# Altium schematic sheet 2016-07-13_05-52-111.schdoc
size 326 x 125 mm; SheetNumber: 1; SheetTotal: 1
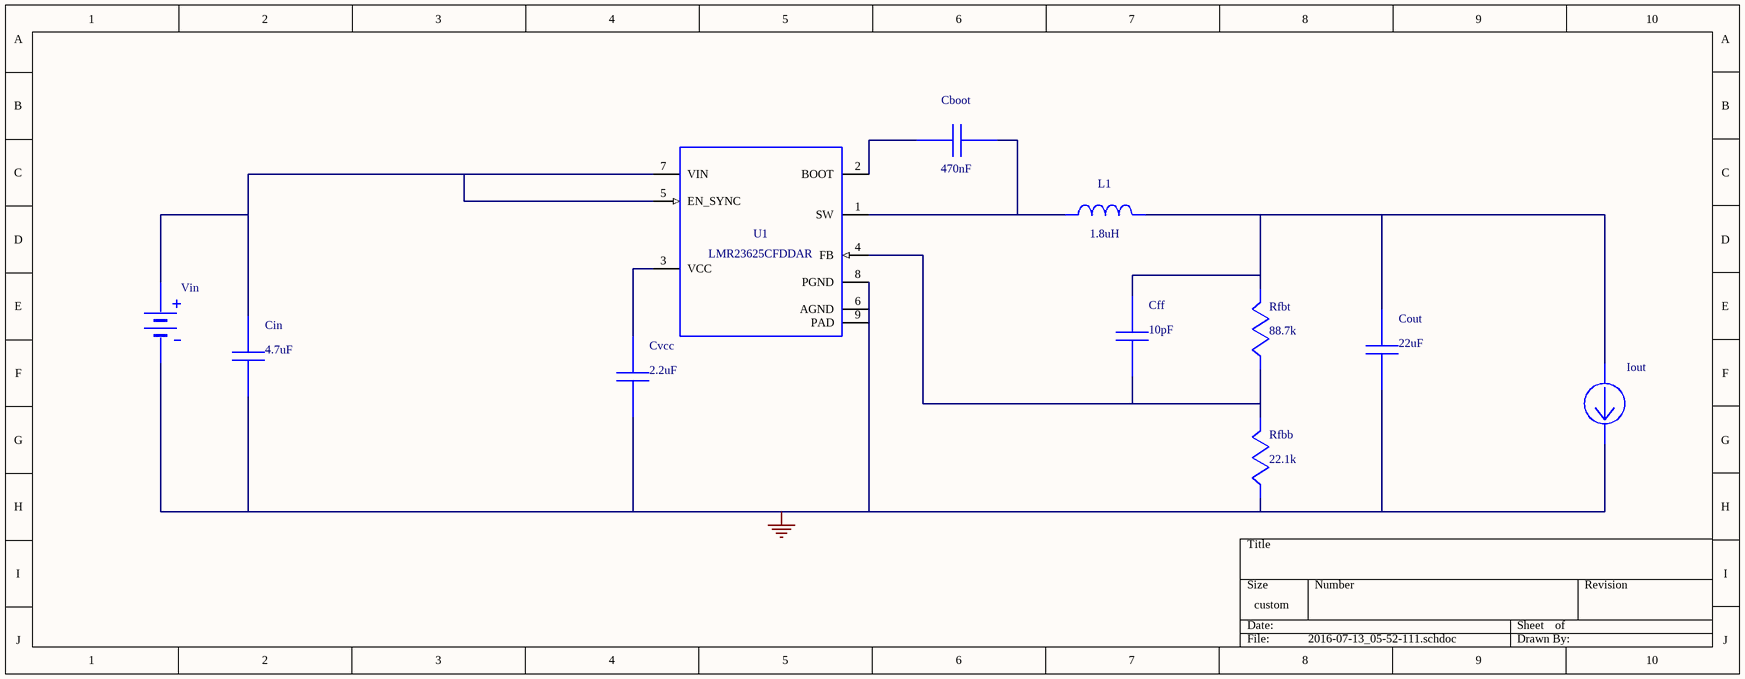
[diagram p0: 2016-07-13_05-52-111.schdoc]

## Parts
Cboot  value 470nF  (hidden comment: GRM188R71E474KA12D)
Cff  value 10pF  (hidden comment: C0805C100M4GACTU)
Cin  value 4.7uF  (hidden comment: GRM32ER71H475KA88L)
Cout  value 22uF  (hidden comment: GRM32ER61C226ME20L)
Cvcc  value 2.2uF  (hidden comment: GRM188R60J225KE19D)
Iout  WB_CURRENT_LOAD  (value not drawn)
L1  value 1.8uH  (hidden comment: SRN6045-1R8Y)
Rfbb  value 22.1k  (hidden comment: ERJ-6ENF2212V)
Rfbt  value 88.7k  (hidden comment: ERJ-6ENF8872V)
U1  LMR23625CFDDAR
Vin  WB_BATTERY  (value not drawn)

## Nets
0: Cin.2 Cout.2 Cvcc.2 Iout.2(-) Rfbb.2 U1.6(AGND) U1.8(PGND) U1.9(PAD) Vin.2(-)
NetCboot_1: Cboot.1 U1.2(BOOT)
NetCboot_2: Cboot.2 L1.1 U1.1(SW)
NetCff_1: Cff.1 Cout.1 Iout.1(+) L1.2 Rfbt.1
NetCff_2: Cff.2 Rfbb.1 Rfbt.2 U1.4(FB)
NetCin_1: Cin.1 U1.5(EN_SYNC) U1.7(VIN) Vin.1(+)
NetCvcc_1: Cvcc.1 U1.3(VCC)

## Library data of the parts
Cboot = GRM188R71E474KA12D: GRM188R71E474KA1; Manufacturer Name: MuRata
Cff = C0805C100M4GACTU: Manufacturer Name: Kemet
Cin = GRM32ER71H475KA88L: GRM32ER71H475KA8; Manufacturer Name: MuRata
Cout = GRM32ER61C226ME20L: GRM32ER61C226ME2; Manufacturer Name: MuRata
Cvcc = GRM188R60J225KE19D: GRM188R60J225KE1; Manufacturer Name: MuRata
L1 = SRN6045-1R8Y: Manufacturer Name: Bourns
Rfbb = ERJ-6ENF2212V: Manufacturer Name: Panasonic
Rfbt = ERJ-6ENF8872V: Manufacturer Name: Panasonic
U1 = LMR23625CFDDAR: Manufacturer Name: Texas Instruments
